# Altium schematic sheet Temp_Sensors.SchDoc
size A4; Organization: HTL Hollabrunn; Address1: Abteilung Elektronik; Address2: Anton Ehrenfried-Straße 10; Address3: 2020 Hollabrunn
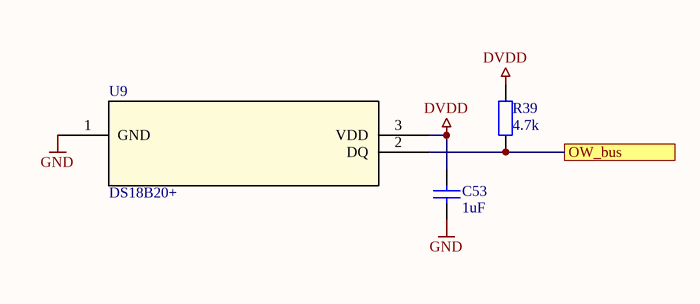
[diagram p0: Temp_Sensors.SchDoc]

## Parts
C53  1uF  [C1206-KUE]
R39  4.7k  [C1206-KUE]
U9  DS18B20+  [21-0248A_Q3-1_MXM]

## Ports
OW_bus

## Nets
DVDD: C53.2 R39.1 U9.3(VDD)
GND: C53.1 U9.1(GND)
OW_bus: R39.2 U9.2(DQ) ; port OW_bus

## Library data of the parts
C53 = Capacitor: Manufacturer: Kemet; Bezeichnung: Kerko +-10% 63V
R39 = ResistorSMD: Resistor SMD; Manufacturer: AVX; Bezeichnung: SMD Wid. 1/8W 2%
U9 = DS18B20+: Programmable Resolution 1-Wire Digital Thermometer; Manufacturer_Name: Analog Devices Inc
